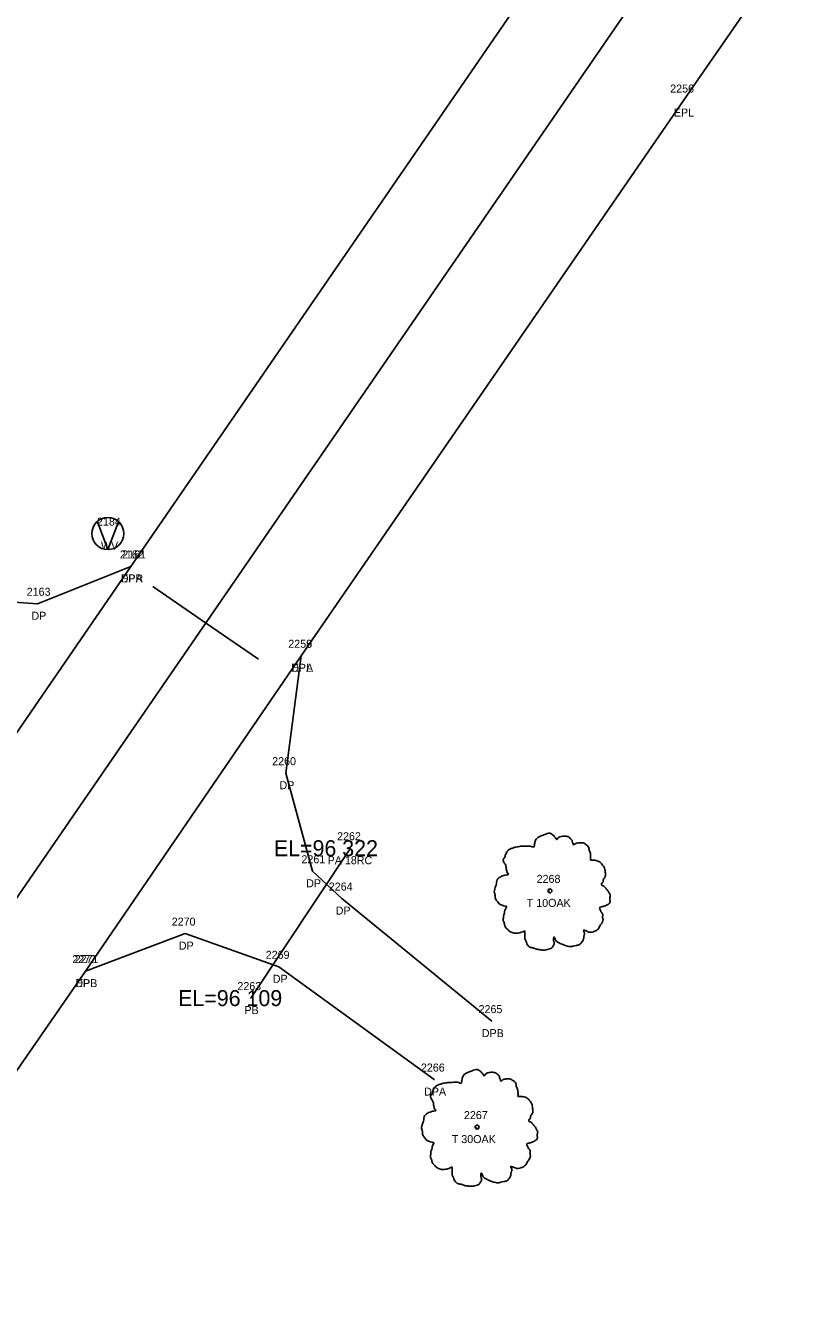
# Model space of a CAD drawing. Extents: x 2266664 to 2272542, y 716533 to 724777.
# Drawn here: x 2271866.2 to 2271962, y 723993.3 to 724151.8 of the extents above; entities that cross this region are included whole.
import ezdxf

# ---------------------------------------------------------------- set-up
doc = ezdxf.new("R2010")
doc.units = 0
for name, color, linetype in [('RD_EX_DR_Pipe', 7, 'Continuous'), ('RD_EX_DR_Pipe_txCode', 7, 'Continuous'), ('RD_EX_Driveway', 7, 'Continuous'), ('RD_EX_Driveway_txCode', 7, 'Continuous'), ('RD_EX_Road', 7, 'Continuous'), ('RD_EX_Road_txCode', 7, 'Continuous'), ('RD_EX_UT', 7, 'Continuous'), ('RD_EX_UT_txCode', 7, 'Continuous'), ('RD_EX_VEG', 7, 'Continuous'), ('RD_EX_VEG_txCode', 7, 'Continuous'), ('RD_HC_Cl', 7, 'Continuous'), ('RD_HC_Data_Tic', 7, 'Continuous'), ('RD_SMD_Locator', 7, 'Continuous'), ('RD_TX_Pipe_ElevEX', 7, 'Continuous')]:
    doc.layers.add(name, color=color, linetype=linetype)

msp = doc.modelspace()

# ---------------------------------------------------------------- linework, layer by layer
at = {"layer": 'RD_EX_DR_Pipe'}
msp.add_line((2271906.83, 724048.94), (2271894.37, 724030.21), dxfattribs=at)
at = {"layer": 'RD_EX_Driveway'}
for points in [[(2271879.39, 724084.16), (2271867.74, 724079.49), (2271856.5, 724080.29), (2271845.33, 724086.1), (2271836.93, 724074.74), (2271850.87, 724063.06), (2271854.45, 724054.18), (2271852.9, 724045.63)], [(2271900.7, 724072.99), (2271898.75, 724058.32), (2271902.09, 724046.06), (2271905.78, 724042.65), (2271924.51, 724027.33)], [(2271917.32, 724020.03), (2271897.9, 724034.12), (2271886.17, 724038.27), (2271873.7, 724033.58)]]:
    msp.add_lwpolyline(points, dxfattribs=at)
at = {"layer": 'RD_EX_Road'}
for points in [[(2272350.52, 724770.05), (2272301.75, 724698.9), (2272265.2, 724646.02), (2272253.02, 724627.92), (2272200.51, 724550.87), (2272147.54, 724474.34), (2272126.28, 724443.66), (2272107.36, 724416.48), (2272092.2, 724393.69), (2272038.42, 724315.2), (2271991.52, 724247.47), (2271974.41, 724222.16), (2271928.73, 724155.87), (2271879.39, 724084.16), (2271852.9, 724045.63), (2271818.37, 723996.02), (2271765.12, 723918.77), (2271712.35, 723841.58), (2271659.05, 723763.61), (2271604.53, 723684.77), (2271550.65, 723606.61)], [(2272368.97, 724754.13), (2272346.57, 724721.92), (2272321.77, 724685.09), (2272273.25, 724614.42), (2272223.01, 724540.91), (2272206.83, 724517.64), (2272178.6, 724477.03), (2272166.48, 724459.37), (2272137.67, 724416.89), (2272108.53, 724374.93), (2272057.89, 724300.99), (2272036.24, 724269.85), (2272022.13, 724249.17), (2272003.16, 724221.27), (2271948.47, 724142.38), (2271900.7, 724072.99), (2271873.7, 724033.58), (2271837.94, 723981.87), (2271784.96, 723904.95), (2271732.12, 723828.06), (2271678.32, 723749.57), (2271627.92, 723676.62), (2271614.21, 723655.35), (2271570.62, 723593.07)]]:
    msp.add_lwpolyline(points, dxfattribs=at)
at = {"layer": 'RD_EX_UT'}
for q in [(2271875.21, 724089.75), (2271877.83, 724089.72)]:
    msp.add_line((2271876.51, 724086.27), q, dxfattribs=at)
msp.add_circle((2271876.51, 724088.26), 2, dxfattribs=at)
at = {"layer": 'RD_EX_VEG'}
for centre, radius in [((2271931.77, 724043.61), 0.25), ((2271931.76, 724043.6), 0.0001), ((2271922.68, 724014.09), 0.25), ((2271922.67, 724014.07), 0.0001)]:
    msp.add_circle(centre, radius, dxfattribs=at)
for points in [[(2271931.9, 724050.78), (2271931.6, 724050.81), (2271931.28, 724050.71), (2271931.03, 724050.61), (2271930.8, 724050.53), (2271930.58, 724050.43), (2271930.28, 724050.26), (2271930.05, 724050.06), (2271929.93, 724049.81), (2271929.88, 724049.58), (2271929.83, 724049.31), (2271929.83, 724049.13), (2271929.7, 724049.11), (2271929.55, 724049.13), (2271929.3, 724049.21), (2271929.05, 724049.21), (2271928.8, 724049.21), (2271928.45, 724049.18), (2271928.1, 724049.18), (2271927.83, 724049.13), (2271927.5, 724049.08), (2271927.13, 724048.96), (2271926.78, 724048.83), (2271926.48, 724048.58), (2271926.23, 724048.11), (2271926.1, 724047.76), (2271925.95, 724047.51), (2271926.1, 724047.06), (2271926.28, 724046.71), (2271926.3, 724046.51), (2271926.38, 724046.08), (2271926.48, 724045.86), (2271926.6, 724045.66), (2271926.53, 724045.63), (2271926.15, 724045.58), (2271925.85, 724045.48), (2271925.43, 724045.26), (2271925.2, 724045.03), (2271925.1, 724044.71), (2271925.08, 724044.36), (2271924.98, 724044.16), (2271924.9, 724043.88), (2271924.88, 724043.81), (2271924.83, 724043.49), (2271924.93, 724043.04), (2271924.95, 724042.69), (2271925.08, 724042.46), (2271925.23, 724042.29), (2271925.4, 724042.04), (2271925.8, 724041.81), (2271926.13, 724041.71), (2271926.33, 724041.69), (2271926.15, 724041.19), (2271926.1, 724040.84), (2271925.98, 724040.44), (2271925.98, 724040.36), (2271925.93, 724039.89), (2271926.08, 724039.56), (2271926.15, 724039.19), (2271926.33, 724038.96), (2271926.6, 724038.66), (2271926.93, 724038.44), (2271927.43, 724038.31), (2271927.83, 724038.34), (2271928.4, 724038.51), (2271928.65, 724038.59), (2271928.63, 724038.41), (2271928.65, 724038.04), (2271928.65, 724037.61), (2271928.8, 724037.29), (2271928.9, 724037.01), (2271929.05, 724036.76), (2271929.38, 724036.54), (2271929.78, 724036.46), (2271930.2, 724036.31), (2271930.65, 724036.24), (2271931.15, 724036.21), (2271931.75, 724036.36), (2271932.03, 724036.49), (2271932.13, 724036.66), (2271932.33, 724037.04), (2271932.28, 724037.26), (2271932.3, 724037.86), (2271932.4, 724037.69), (2271932.58, 724037.34), (2271933.08, 724037.04), (2271933.48, 724036.86), (2271933.95, 724036.71), (2271934.25, 724036.64), (2271934.72, 724036.71), (2271935.1, 724036.79), (2271935.47, 724036.91), (2271935.77, 724037.19), (2271935.95, 724037.46), (2271936, 724037.74), (2271936.07, 724038.11), (2271936.12, 724038.29)], [(2271936.12, 724038.29), (2271936.05, 724038.46), (2271936, 724038.71), (2271936.07, 724038.69), (2271936.25, 724038.64), (2271936.52, 724038.51), (2271936.75, 724038.44), (2271937.07, 724038.46), (2271937.35, 724038.56), (2271937.8, 724038.84), (2271938.07, 724039.31), (2271938.35, 724039.71), (2271938.42, 724040.04), (2271938.37, 724040.26), (2271938.35, 724040.76), (2271938.15, 724041.01), (2271938.1, 724041.14), (2271938, 724041.54), (2271938.07, 724041.59), (2271938.35, 724041.64), (2271938.72, 724041.76), (2271939, 724041.89), (2271939.22, 724042.06), (2271939.3, 724042.29), (2271939.27, 724042.69), (2271939.32, 724043.09), (2271939.25, 724043.24), (2271939.15, 724043.39), (2271939.07, 724043.59), (2271938.92, 724043.73), (2271938.82, 724043.88), (2271938.72, 724043.98), (2271938.6, 724044.13), (2271938.42, 724044.26), (2271938.27, 724044.31), (2271938.22, 724044.46), (2271938.37, 724044.66), (2271938.42, 724044.76), (2271938.45, 724044.98), (2271938.67, 724045.33), (2271938.72, 724045.73), (2271938.67, 724046.16), (2271938.62, 724046.43), (2271938.47, 724046.71), (2271938.27, 724046.96), (2271938.15, 724047.13), (2271937.97, 724047.26), (2271937.65, 724047.38), (2271937.4, 724047.43), (2271937.05, 724047.43), (2271936.85, 724047.48), (2271936.87, 724047.53), (2271936.87, 724047.68), (2271936.87, 724047.96), (2271936.8, 724048.41), (2271936.65, 724048.91), (2271936.65, 724048.93), (2271936.55, 724049.18), (2271936.32, 724049.38), (2271936.15, 724049.48), (2271935.95, 724049.61), (2271935.7, 724049.63), (2271935.4, 724049.63), (2271935.12, 724049.58), (2271934.92, 724049.48), (2271934.75, 724049.36), (2271934.67, 724049.51), (2271934.57, 724049.81), (2271934.52, 724049.96), (2271934.37, 724050.13), (2271934.15, 724050.33), (2271933.7, 724050.46), (2271933.08, 724050.38), (2271932.78, 724050.18), (2271932.63, 724050.01), (2271932.58, 724050.13), (2271932.38, 724050.33), (2271932.28, 724050.51), (2271932.1, 724050.63), (2271931.95, 724050.73), (2271931.85, 724050.78)], [(2271922.82, 724021.26), (2271922.52, 724021.29), (2271922.19, 724021.19), (2271921.94, 724021.09), (2271921.72, 724021.01), (2271921.49, 724020.91), (2271921.19, 724020.74), (2271920.97, 724020.54), (2271920.84, 724020.29), (2271920.79, 724020.06), (2271920.74, 724019.79), (2271920.74, 724019.61), (2271920.62, 724019.59), (2271920.47, 724019.61), (2271920.22, 724019.69), (2271919.97, 724019.69), (2271919.72, 724019.69), (2271919.37, 724019.66), (2271919.02, 724019.66), (2271918.74, 724019.61), (2271918.42, 724019.56), (2271918.04, 724019.44), (2271917.69, 724019.31), (2271917.39, 724019.06), (2271917.14, 724018.59), (2271917.02, 724018.24), (2271916.87, 724017.99), (2271917.02, 724017.54), (2271917.19, 724017.19), (2271917.22, 724016.99), (2271917.29, 724016.56), (2271917.39, 724016.34), (2271917.52, 724016.14), (2271917.44, 724016.11), (2271917.07, 724016.06), (2271916.77, 724015.96), (2271916.34, 724015.74), (2271916.12, 724015.51), (2271916.02, 724015.19), (2271915.99, 724014.84), (2271915.89, 724014.64), (2271915.82, 724014.36), (2271915.79, 724014.29), (2271915.74, 724013.96), (2271915.84, 724013.51), (2271915.87, 724013.16), (2271915.99, 724012.94), (2271916.14, 724012.76), (2271916.32, 724012.51), (2271916.72, 724012.29), (2271917.04, 724012.19), (2271917.24, 724012.16), (2271917.07, 724011.66), (2271917.02, 724011.32), (2271916.89, 724010.92), (2271916.89, 724010.84), (2271916.84, 724010.37), (2271916.99, 724010.04), (2271917.07, 724009.67), (2271917.24, 724009.44), (2271917.52, 724009.14), (2271917.84, 724008.92), (2271918.34, 724008.79), (2271918.74, 724008.82), (2271919.32, 724008.99), (2271919.57, 724009.07), (2271919.54, 724008.89), (2271919.57, 724008.52), (2271919.57, 724008.09), (2271919.72, 724007.77), (2271919.82, 724007.49), (2271919.97, 724007.24), (2271920.29, 724007.02), (2271920.69, 724006.94), (2271921.12, 724006.79), (2271921.57, 724006.72), (2271922.07, 724006.69), (2271922.67, 724006.84), (2271922.94, 724006.97), (2271923.04, 724007.14), (2271923.24, 724007.52), (2271923.19, 724007.74), (2271923.21, 724008.34), (2271923.31, 724008.17), (2271923.49, 724007.82), (2271923.99, 724007.52), (2271924.39, 724007.34), (2271924.86, 724007.19), (2271925.16, 724007.12), (2271925.64, 724007.19), (2271926.01, 724007.27), (2271926.39, 724007.39), (2271926.69, 724007.67), (2271926.86, 724007.94), (2271926.91, 724008.22), (2271926.99, 724008.59), (2271927.04, 724008.77)], [(2271927.04, 724008.77), (2271926.96, 724008.94), (2271926.91, 724009.19), (2271926.99, 724009.17), (2271927.16, 724009.12), (2271927.44, 724008.99), (2271927.66, 724008.92), (2271927.99, 724008.94), (2271928.26, 724009.04), (2271928.71, 724009.32), (2271928.99, 724009.79), (2271929.26, 724010.19), (2271929.34, 724010.52), (2271929.29, 724010.74), (2271929.26, 724011.24), (2271929.06, 724011.49), (2271929.01, 724011.61), (2271928.91, 724012.01), (2271928.99, 724012.06), (2271929.26, 724012.11), (2271929.64, 724012.24), (2271929.91, 724012.36), (2271930.14, 724012.54), (2271930.21, 724012.76), (2271930.19, 724013.16), (2271930.24, 724013.56), (2271930.16, 724013.71), (2271930.06, 724013.86), (2271929.99, 724014.06), (2271929.84, 724014.21), (2271929.74, 724014.36), (2271929.64, 724014.46), (2271929.51, 724014.61), (2271929.34, 724014.74), (2271929.19, 724014.79), (2271929.14, 724014.94), (2271929.29, 724015.14), (2271929.34, 724015.24), (2271929.36, 724015.46), (2271929.59, 724015.81), (2271929.64, 724016.21), (2271929.59, 724016.64), (2271929.54, 724016.91), (2271929.39, 724017.19), (2271929.19, 724017.44), (2271929.06, 724017.61), (2271928.89, 724017.74), (2271928.56, 724017.86), (2271928.31, 724017.91), (2271927.96, 724017.91), (2271927.76, 724017.96), (2271927.79, 724018.01), (2271927.79, 724018.16), (2271927.79, 724018.44), (2271927.71, 724018.89), (2271927.56, 724019.39), (2271927.56, 724019.41), (2271927.46, 724019.66), (2271927.24, 724019.86), (2271927.06, 724019.96), (2271926.86, 724020.09), (2271926.61, 724020.11), (2271926.31, 724020.11), (2271926.04, 724020.06), (2271925.84, 724019.96), (2271925.66, 724019.84), (2271925.59, 724019.99), (2271925.49, 724020.29), (2271925.44, 724020.44), (2271925.29, 724020.61), (2271925.06, 724020.81), (2271924.61, 724020.94), (2271923.99, 724020.86), (2271923.69, 724020.66), (2271923.54, 724020.49), (2271923.49, 724020.61), (2271923.29, 724020.81), (2271923.19, 724020.99), (2271923.02, 724021.11), (2271922.87, 724021.21), (2271922.77, 724021.26)]]:
    msp.add_spline(points, degree=3, dxfattribs=at)
at = {"layer": 'RD_HC_Cl'}
msp.add_line((2267342.91, 717471.2), (2272360.46, 724762.59), dxfattribs=at)
at = {"layer": 'RD_HC_Data_Tic'}
for q in [(2271882.15, 724081.64), (2271895.33, 724072.57)]:
    msp.add_line((2271888.74, 724077.1), q, dxfattribs=at)
at = {"layer": 'RD_SMD_Locator'}
for centre in [(2271948.47, 724142.38), (2271879.39, 724084.16), (2271879.39, 724084.16), (2271867.74, 724079.49), (2271900.7, 724072.99), (2271900.7, 724072.99), (2271898.75, 724058.32), (2271906.83, 724048.94), (2271902.09, 724046.06), (2271905.78, 724042.65), (2271886.17, 724038.27), (2271873.7, 724033.58), (2271873.7, 724033.58), (2271897.9, 724034.12), (2271894.37, 724030.21), (2271924.51, 724027.33), (2271917.32, 724020.03)]:
    msp.add_circle(centre, 0.001, dxfattribs=at)

# ---------------------------------------------------------------- texts
at = {"layer": 'RD_EX_DR_Pipe_txCode'}
for s, p in [('2262', (2271905.17, 724049.94)), ('PA 18RC', (2271903.99, 724046.94)), ('2263', (2271892.71, 724031.21)), ('PB', (2271893.59, 724028.21))]:
    msp.add_text(s, height=1, dxfattribs=at).set_placement(p)
at = {"layer": 'RD_EX_Driveway_txCode'}
for s, p in [('2162', (2271878.02, 724085.16)), ('DPA', (2271878.13, 724082.16)), ('2163', (2271866.37, 724080.49)), ('DP', (2271866.96, 724077.49)), ('2259', (2271899.07, 724073.99)), ('DPA', (2271899.43, 724070.99)), ('2260', (2271897.06, 724059.32)), ('DP', (2271897.97, 724056.32)), ('2261', (2271900.72, 724047.06)), ('DP', (2271901.31, 724044.06)), ('2264', (2271904.13, 724043.65)), ('DP', (2271905, 724040.65)), ('2270', (2271884.5, 724039.27)), ('DP', (2271885.39, 724036.27)), ('2271', (2271872.36, 724034.58)), ('2269', (2271896.25, 724035.12)), ('DPB', (2271872.45, 724031.58)), ('DP', (2271897.13, 724032.12)), ('2265', (2271922.86, 724028.33)), ('DPB', (2271923.26, 724025.33)), ('2266', (2271915.65, 724021.03)), ('DPA', (2271916.05, 724018.03))]:
    msp.add_text(s, height=1, dxfattribs=at).set_placement(p)
at = {"layer": 'RD_EX_Road_txCode'}
for s, p in [('2256', (2271946.82, 724143.38)), ('EPL', (2271947.27, 724140.38)), ('2161', (2271878.31, 724085.16)), ('EPR', (2271878.17, 724082.16)), ('2258', (2271899.07, 724073.99)), ('EPL', (2271899.5, 724070.99)), ('2272', (2271872.07, 724034.58)), ('EPL', (2271872.5, 724031.58))]:
    msp.add_text(s, height=1, dxfattribs=at).set_placement(p)
at = {"layer": 'RD_EX_UT_txCode'}
for s, p in [('2184', (2271875.16, 724089.26)), ('WV', (2271875.65, 724086.26))]:
    msp.add_text(s, height=1, dxfattribs=at).set_placement(p)
at = {"layer": 'RD_EX_VEG_txCode'}
for s, p in [('2268', (2271930.12, 724044.61)), ('T 10OAK', (2271928.88, 724041.61)), ('2267', (2271921.03, 724015.09)), ('T 30OAK', (2271919.51, 724012.09))]:
    msp.add_text(s, height=1, dxfattribs=at).set_placement(p)
at = {"layer": 'RD_TX_Pipe_ElevEX'}
for s, p in [('EL=96 322  ', (2271897.27, 724047.94)), ('EL=96 109  ', (2271885.3, 724029.21))]:
    msp.add_text(s, height=2, dxfattribs=at).set_placement(p)

doc.saveas('drawing.dxf')
